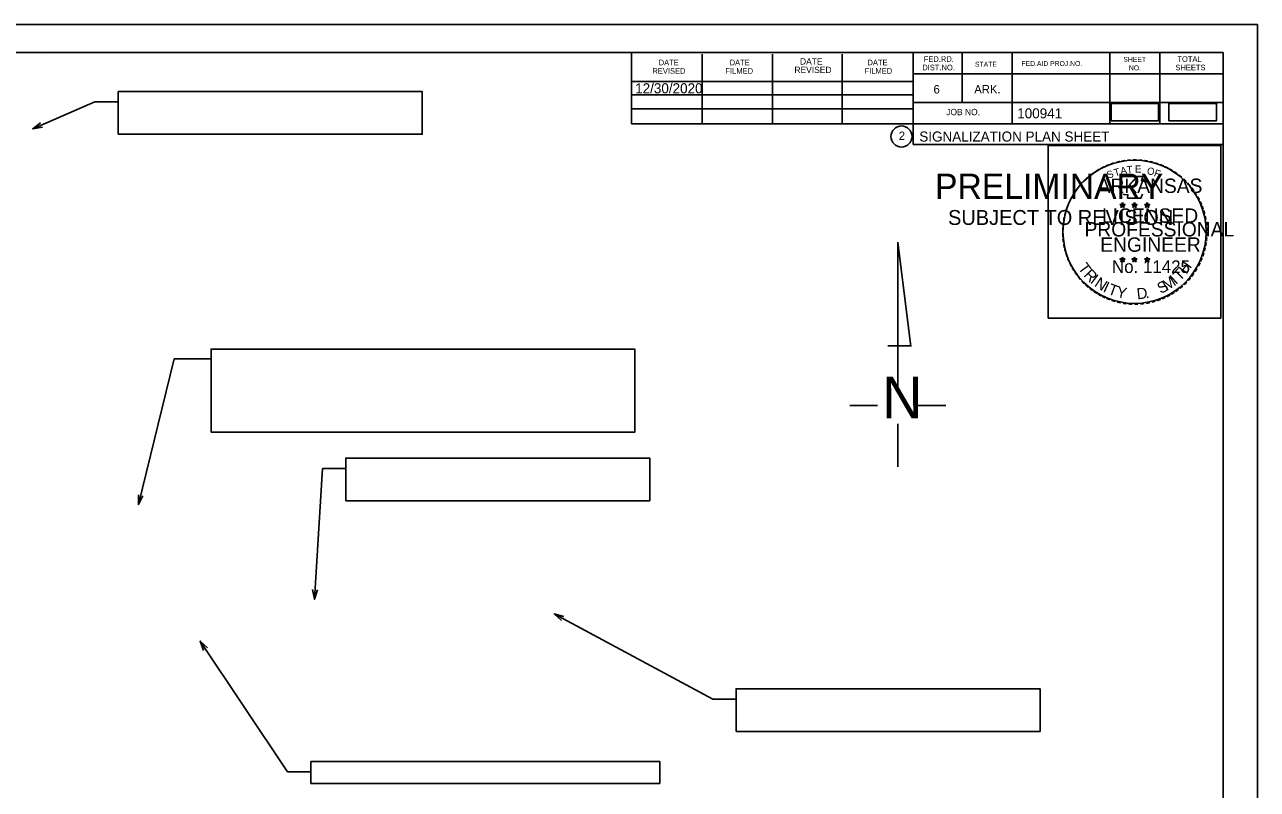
# Model space of a CAD drawing. Extents: x 1845362 to 1846362, y 750211 to 750851.
# Drawn here: x 1845848 to 1846362, y 750532 to 750851 of the extents above; entities that cross this region are included whole.
import ezdxf

# ---------------------------------------------------------------- set-up
doc = ezdxf.new("R2010")
doc.units = 0
for name, color, linetype in [('R_Border', 7, 'Continuous'), ('R_Border PE', 7, 'Continuous'), ('R_Border Prem', 7, 'Continuous'), ('R_Dimension', 7, 'Continuous'), ('R_Draft', 7, 'Continuous'), ('R_No Plot', 7, 'Continuous'), ('T_Drafting', 7, 'Continuous')]:
    doc.layers.add(name, color=color, linetype=linetype)

msp = doc.modelspace()

# ---------------------------------------------------------------- linework, layer by layer
at = {"layer": 'R_Border'}
for p, q in [((1845398.86, 750839.27), (1846347.4, 750839.27)), ((1845856.42, 750838.49), (1845856.42, 750838.49)), ((1845856.42, 750838.49), (1845856.42, 750838.49)), ((1846100.62, 750809.63), (1846100.62, 750839.27)), ((1846130.2, 750809.63), (1846130.2, 750838.67)), ((1846159.48, 750809.63), (1846159.48, 750838.67)), ((1846188.52, 750809.63), (1846188.52, 750838.67)), ((1846218.1, 750839.27), (1846218.1, 750800.87)), ((1846238.62, 750839.27), (1846238.62, 750818.45)), ((1846259.44, 750839.27), (1846259.44, 750809.63)), ((1846300.18, 750839.27), (1846300.18, 750809.63)), ((1846321, 750839.27), (1846321, 750809.63)), ((1846347.4, 750222.89), (1846347.4, 750839.27)), ((1846347.4, 750830.45), (1846218.1, 750830.45)), ((1846347.4, 750830.51), (1846347.4, 750830.51)), ((1846100.62, 750827.21), (1846218.1, 750827.21)), ((1846100.62, 750821.63), (1846218.1, 750821.63)), ((1846347.4, 750818.45), (1846218.1, 750818.45)), ((1846226.98, 750818.45), (1846347.4, 750818.45)), ((1846100.62, 750809.63), (1846100.62, 750815.81)), ((1846100.62, 750815.81), (1846218.1, 750815.81)), ((1846347.4, 750809.63), (1846100.62, 750809.63)), ((1846218.1, 750800.87), (1846347.4, 750800.87))]:
    msp.add_line(p, q, dxfattribs=at)
msp.add_circle((1846213.26, 750804.27), 4.4, dxfattribs=at)
at = {"layer": 'R_Border PE'}
for p, q in [((1846305.43, 750776.71), (1846305.3, 750775.95)), ((1846305.43, 750775.62), (1846305.43, 750776.71)), ((1846305.43, 750776.71), (1846305.57, 750775.96)), ((1846310.44, 750776.71), (1846310.31, 750775.95)), ((1846310.44, 750775.62), (1846310.44, 750776.71)), ((1846310.44, 750776.71), (1846310.58, 750775.96)), ((1846315.73, 750776.67), (1846315.61, 750775.92)), ((1846315.73, 750775.58), (1846315.73, 750776.67)), ((1846315.73, 750776.67), (1846315.88, 750775.92)), ((1846304.38, 750775.95), (1846305.43, 750775.62)), ((1846304.38, 750775.95), (1846305.14, 750775.81)), ((1846304.38, 750775.95), (1846305.09, 750775.58)), ((1846304.78, 750774.72), (1846305.43, 750775.62)), ((1846304.78, 750774.72), (1846305.16, 750775.46)), ((1846304.78, 750774.72), (1846305.42, 750775.38)), ((1846306.07, 750774.72), (1846305.42, 750775.37)), ((1846306.47, 750775.95), (1846305.43, 750775.62)), ((1846306.07, 750774.72), (1846305.43, 750775.62)), ((1846306.47, 750775.95), (1846305.61, 750775.8)), ((1846306.07, 750774.72), (1846305.65, 750775.6)), ((1846306.47, 750775.95), (1846305.86, 750775.64)), ((1846309.39, 750775.95), (1846310.44, 750775.62)), ((1846309.39, 750775.95), (1846310.15, 750775.81)), ((1846309.39, 750775.95), (1846310.1, 750775.58)), ((1846309.79, 750774.72), (1846310.44, 750775.62)), ((1846309.79, 750774.72), (1846310.17, 750775.46)), ((1846309.79, 750774.72), (1846310.43, 750775.38)), ((1846311.08, 750774.72), (1846310.43, 750775.37)), ((1846311.48, 750775.95), (1846310.44, 750775.62)), ((1846311.08, 750774.72), (1846310.44, 750775.62)), ((1846311.48, 750775.95), (1846310.62, 750775.8)), ((1846311.08, 750774.72), (1846310.66, 750775.6)), ((1846311.48, 750775.95), (1846310.87, 750775.64)), ((1846314.68, 750775.91), (1846315.73, 750775.58)), ((1846314.68, 750775.91), (1846315.44, 750775.78)), ((1846314.68, 750775.91), (1846315.39, 750775.55)), ((1846315.08, 750774.69), (1846315.73, 750775.58)), ((1846315.08, 750774.69), (1846315.46, 750775.42)), ((1846315.08, 750774.69), (1846315.72, 750775.34)), ((1846316.37, 750774.69), (1846315.72, 750775.33)), ((1846316.77, 750775.91), (1846315.73, 750775.58)), ((1846316.37, 750774.69), (1846315.73, 750775.58)), ((1846316.77, 750775.91), (1846315.91, 750775.77)), ((1846316.37, 750774.69), (1846315.96, 750775.56)), ((1846316.77, 750775.91), (1846316.16, 750775.61)), ((1846304.37, 750753.23), (1846305.41, 750752.9)), ((1846304.37, 750753.23), (1846305.13, 750753.09)), ((1846304.37, 750753.23), (1846305.08, 750752.86)), ((1846304.77, 750752.01), (1846305.41, 750752.9)), ((1846304.77, 750752.01), (1846305.14, 750752.74)), ((1846304.77, 750752.01), (1846305.41, 750752.66)), ((1846305.41, 750753.99), (1846305.29, 750753.24)), ((1846305.41, 750752.9), (1846305.41, 750753.99)), ((1846305.41, 750753.99), (1846305.56, 750753.24)), ((1846306.46, 750753.23), (1846305.41, 750752.9)), ((1846306.05, 750752.01), (1846305.41, 750752.9)), ((1846306.05, 750752.01), (1846305.41, 750752.65)), ((1846306.46, 750753.23), (1846305.6, 750753.08)), ((1846306.05, 750752.01), (1846305.64, 750752.88)), ((1846306.46, 750753.23), (1846305.84, 750752.92)), ((1846309.37, 750753.23), (1846310.42, 750752.9)), ((1846309.37, 750753.23), (1846310.13, 750753.09)), ((1846309.37, 750753.23), (1846310.09, 750752.86)), ((1846309.77, 750752.01), (1846310.42, 750752.9)), ((1846309.77, 750752.01), (1846310.15, 750752.74)), ((1846309.77, 750752.01), (1846310.42, 750752.66)), ((1846310.42, 750753.99), (1846310.3, 750753.24)), ((1846310.42, 750752.9), (1846310.42, 750753.99)), ((1846310.42, 750753.99), (1846310.57, 750753.24)), ((1846311.46, 750753.23), (1846310.42, 750752.9)), ((1846311.06, 750752.01), (1846310.42, 750752.9)), ((1846311.06, 750752.01), (1846310.42, 750752.65)), ((1846311.46, 750753.23), (1846310.6, 750753.08)), ((1846311.06, 750752.01), (1846310.65, 750752.88)), ((1846311.46, 750753.23), (1846310.85, 750752.92)), ((1846314.68, 750753.2), (1846315.72, 750752.87)), ((1846314.68, 750753.2), (1846315.43, 750753.06)), ((1846314.68, 750753.2), (1846315.39, 750752.83)), ((1846315.07, 750751.98), (1846315.72, 750752.87)), ((1846315.07, 750751.98), (1846315.45, 750752.71)), ((1846315.07, 750751.98), (1846315.72, 750752.63)), ((1846315.72, 750753.96), (1846315.6, 750753.21)), ((1846315.72, 750752.87), (1846315.72, 750753.96)), ((1846315.72, 750753.96), (1846315.87, 750753.21)), ((1846316.76, 750753.2), (1846315.72, 750752.87)), ((1846316.36, 750751.98), (1846315.72, 750752.87)), ((1846316.36, 750751.98), (1846315.72, 750752.62)), ((1846316.76, 750753.2), (1846315.91, 750753.05)), ((1846316.36, 750751.98), (1846315.95, 750752.85)), ((1846316.76, 750753.2), (1846316.15, 750752.89))]:
    msp.add_line(p, q, dxfattribs=at)
for points in [[(1846304.5, 750787.58), (1846305.31, 750785.1)], [(1846315.04, 750784.82), (1846315.46, 750785.67), (1846313.41, 750785.6), (1846313.85, 750787.58), (1846304.5, 750787.58)], [(1846305.43, 750776.71), (1846306.07, 750774.72), (1846304.38, 750775.95), (1846306.47, 750775.95), (1846304.78, 750774.72), (1846305.43, 750776.71)], [(1846305.98, 750780.31), (1846305.98, 750780.05), (1846307.67, 750780), (1846307.51, 750778.58), (1846313.12, 750778.58), (1846313.72, 750780.18)], [(1846310.44, 750776.71), (1846311.08, 750774.72), (1846309.39, 750775.95), (1846311.48, 750775.95), (1846309.79, 750774.72), (1846310.44, 750776.71)], [(1846315.73, 750776.67), (1846316.37, 750774.69), (1846314.68, 750775.91), (1846316.77, 750775.91), (1846315.08, 750774.69), (1846315.73, 750776.67)], [(1846305.41, 750753.99), (1846306.05, 750752.01), (1846304.37, 750753.23), (1846306.46, 750753.23), (1846304.77, 750752.01), (1846305.41, 750753.99)], [(1846310.42, 750753.99), (1846311.06, 750752.01), (1846309.37, 750753.23), (1846311.46, 750753.23), (1846309.77, 750752.01), (1846310.42, 750753.99)], [(1846315.72, 750753.96), (1846316.36, 750751.98), (1846314.68, 750753.2), (1846316.76, 750753.2), (1846315.07, 750751.98), (1846315.72, 750753.96)]]:
    msp.add_lwpolyline(points, dxfattribs=at)
for centre, radius in [((1846305.42, 750775.61), 0.517), ((1846305.42, 750775.61), 0.434), ((1846305.42, 750775.61), 0.347), ((1846305.42, 750775.61), 0.297), ((1846305.42, 750775.61), 0.224), ((1846305.42, 750775.61), 0.149), ((1846305.42, 750775.61), 0.0889), ((1846310.43, 750775.61), 0.517), ((1846310.43, 750775.61), 0.434), ((1846310.43, 750775.61), 0.347), ((1846310.43, 750775.61), 0.297), ((1846310.43, 750775.61), 0.224), ((1846310.43, 750775.61), 0.149), ((1846310.43, 750775.61), 0.0889), ((1846315.73, 750775.58), 0.517), ((1846315.73, 750775.58), 0.434), ((1846315.73, 750775.58), 0.347), ((1846315.73, 750775.58), 0.297), ((1846315.73, 750775.58), 0.224), ((1846315.73, 750775.58), 0.149), ((1846315.73, 750775.58), 0.0889), ((1846305.41, 750752.89), 0.517), ((1846305.41, 750752.89), 0.434), ((1846305.41, 750752.89), 0.347), ((1846305.41, 750752.89), 0.297), ((1846305.41, 750752.89), 0.224), ((1846305.41, 750752.89), 0.149), ((1846305.41, 750752.89), 0.0889), ((1846310.42, 750752.89), 0.517), ((1846310.42, 750752.89), 0.434), ((1846310.42, 750752.89), 0.347), ((1846310.42, 750752.89), 0.297), ((1846310.42, 750752.89), 0.224), ((1846310.42, 750752.89), 0.149), ((1846310.42, 750752.89), 0.0889), ((1846315.72, 750752.86), 0.517), ((1846315.72, 750752.86), 0.434), ((1846315.72, 750752.86), 0.347), ((1846315.72, 750752.86), 0.297), ((1846315.72, 750752.86), 0.224), ((1846315.72, 750752.86), 0.149), ((1846315.72, 750752.86), 0.0889)]:
    msp.add_circle(centre, radius, dxfattribs=at)
at = {"layer": 'R_Dimension'}
for p, q in [((1845876.89, 750818.68), (1845851, 750807.51)), ((1845876.89, 750818.68), (1845886.64, 750818.68)), ((1845895.03, 750650.68), (1845909.94, 750711.48)), ((1845925.17, 750711.48), (1845909.94, 750711.48)), ((1845971.77, 750665.75), (1845968.42, 750611.21)), ((1845971.77, 750665.75), (1845981.52, 750665.75)), ((1846134.54, 750569.52), (1846068.43, 750605.06)), ((1845957.26, 750539.13), (1845920.84, 750593.72)), ((1846134.54, 750569.52), (1846144.29, 750569.52)), ((1845957.26, 750539.13), (1845967.01, 750539.13))]:
    msp.add_line(p, q, dxfattribs=at)
for points in [[(1845855.06, 750808.18), (1845851, 750807.51), (1845854.27, 750810.02)], [(1845895.01, 750654.8), (1845895.03, 750650.68), (1845896.95, 750654.33)], [(1845969.66, 750615.14), (1845968.42, 750611.21), (1845967.67, 750615.26)], [(1846071.48, 750602.29), (1846068.43, 750605.06), (1846072.42, 750604.05)], [(1845922.23, 750589.84), (1845920.84, 750593.72), (1845923.89, 750590.95)]]:
    msp.add_lwpolyline(points, dxfattribs=at)
at = {"layer": 'R_Draft'}
for p, q in [((1846211.74, 750760.24), (1846217.21, 750716.6)), ((1846211.74, 750699.23), (1846211.74, 750760.24)), ((1846207.51, 750716.93), (1846217.21, 750716.93)), ((1846191.68, 750692.04), (1846203.25, 750692.04)), ((1846219.45, 750692.04), (1846231.81, 750692.04)), ((1846211.74, 750666.5), (1846211.74, 750684.44))]:
    msp.add_line(p, q, dxfattribs=at)
at = {"layer": 'R_No Plot'}
for p, q in [((1845361.65, 750850.95), (1846361.65, 750850.95)), ((1846274.23, 750731.82), (1846274.23, 750731.82))]:
    msp.add_line(p, q, dxfattribs=at)
for points in [[(1845361.63, 750850.95), (1846361.65, 750850.95), (1846361.65, 750210.94), (1845361.63, 750210.94)], [(1846274.46, 750800.5), (1846346.46, 750800.5), (1846346.46, 750728.5), (1846274.46, 750728.5)]]:
    msp.add_lwpolyline(points, close=True, dxfattribs=at)
msp.add_circle((1846310.46, 750764.5), 29.86, dxfattribs=at)
at = {"layer": 'T_Drafting'}
for points in [[(1845886.64, 750805.22), (1846013.38, 750805.22), (1846013.38, 750823.02), (1845886.64, 750823.02)], [(1846300.71, 750810.78), (1846320.46, 750810.78), (1846320.46, 750818.07), (1846300.71, 750818.07)], [(1846324.81, 750810.78), (1846344.56, 750810.78), (1846344.56, 750818.07), (1846324.81, 750818.07)], [(1845925.38, 750680.87), (1846102.04, 750680.87), (1846102.04, 750715.6), (1845925.38, 750715.6)], [(1845981.52, 750652.29), (1846108.26, 750652.29), (1846108.26, 750670.09), (1845981.52, 750670.09)], [(1846144.29, 750556.06), (1846271.03, 750556.06), (1846271.03, 750573.86), (1846144.29, 750573.86)], [(1845967.01, 750534.35), (1846112.42, 750534.35), (1846112.42, 750543.47), (1845967.01, 750543.47)]]:
    msp.add_lwpolyline(points, close=True, dxfattribs=at)

# ---------------------------------------------------------------- texts
at = {"layer": 'R_Border'}
for s, height, p in [('DATE', 2.346, (1846112.02, 750833.99)), ('DATE', 2.346, (1846141.6, 750833.99)), ('REVISED', 2.638, (1846168.6, 750830.75)), ('DATE', 2.638, (1846170.94, 750834.29)), ('DATE', 2.346, (1846199.08, 750833.99)), ('DIST.NO.', 2.346, (1846221.94, 750831.89)), ('FED.RD.', 2.346, (1846222.54, 750835.43)), ('STATE', 2.052, (1846243.9, 750833.39)), ('FED.AID PROJ.NO.', 2.052, (1846263.28, 750833.69)), ('SHEET', 2.052, (1846305.76, 750835.43)), ('NO.', 2.052, (1846308.1, 750831.89)), ('SHEETS', 2.346, (1846327.48, 750831.89)), ('TOTAL', 2.346, (1846328.32, 750835.43)), ('REVISED', 2.346, (1846109.38, 750830.45)), ('FILMED', 2.346, (1846139.86, 750830.45)), ('FILMED', 2.346, (1846197.88, 750830.45)), ('12/30/2020', 4.2, (1846102.19, 750822.29)), ('6', 3.52, (1846226.62, 750822.23)), ('ARK.', 3.517, (1846243.6, 750822.23)), ('JOB NO.', 2.638, (1846231.9, 750813.17)), ('100941', 4.2, (1846261.52, 750811.84)), ('2', 3.52, (1846212.11, 750802.81)), ('SIGNALIZATION PLAN SHEET', 4.2, (1846220.69, 750802.16))]:
    msp.add_text(s, height=height, dxfattribs=at).set_placement(p)
at = {"layer": 'R_Border PE'}
for s, height, rotation, p in [('-', 4.8, 28.7918, (1846296.95, 750789.21)), ('-', 4.8, 24.3072, (1846298.84, 750790.16)), ('-', 4.8, 19.1761, (1846300.75, 750790.96)), ('-', 4.8, 13.6302, (1846303, 750791.69)), ('-', 4.8, 10.2193, (1846305.03, 750792.17)), ('T', 3, 6.0228, (1846307.33, 750788.86)), ('-', 4.8, 5.8968, (1846307.22, 750792.5)), ('-', 4.8, 0.1862, (1846309.53, 750792.72)), ('E', 3, 0.8323, (1846310.65, 750789.19)), ('-', 4.8, 357.743, (1846311.7, 750792.68)), ('-', 4.8, 352.1617, (1846313.93, 750792.51)), ('-', 4.8, 347.2049, (1846316.09, 750792.17)), ('-', 4.8, 342.3362, (1846318, 750791.7)), ('-', 4.8, 337.8551, (1846320.2, 750791.04)), ('-', 4.8, 334.1211, (1846322.09, 750790.22)), ('-', 4.8, 42.9622, (1846290.69, 750784.53)), ('-', 4.8, 38.9507, (1846291.99, 750785.78)), ('-', 4.8, 36.2317, (1846293.42, 750786.91)), ('-', 4.8, 34.0636, (1846295.15, 750788.1)), ('S', 3, 21.594, (1846299.57, 750786.62)), ('T', 3, 16.4036, (1846302.31, 750787.61)), ('A', 3, 11.2132, (1846304.79, 750788.36)), ('O', 3, 350.4515, (1846315.46, 750788.56)), ('F', 3, 340.0707, (1846318.32, 750787.88)), ('-', 4.8, 329.6409, (1846323.83, 750789.37)), ('-', 4.8, 325.8627, (1846325.76, 750788.29)), ('-', 4.8, 320.5297, (1846327.59, 750787.01)), ('-', 4.8, 315.5786, (1846329.39, 750785.55)), ('-', 4.8, 54.2325, (1846286.9, 750779.93)), ('-', 4.8, 50.6142, (1846288.14, 750781.63)), ('-', 4.8, 48.4231, (1846289.35, 750783.09)), ('-', 4.8, 309.8797, (1846331.09, 750783.9)), ('-', 4.8, 306.6522, (1846332.67, 750782.09)), ('-', 4.8, 67.7743, (1846284.21, 750774.68)), ('-', 4.8, 62.8713, (1846284.99, 750776.51)), ('-', 4.8, 58.0706, (1846285.93, 750778.35)), ('-', 4.2, 303.6753, (1846334.13, 750780.39)), ('-', 4.8, 299.6684, (1846335.08, 750778.57)), ('-', 4.8, 294.6628, (1846336.06, 750776.73)), ('-', 4.8, 75.461, (1846282.96, 750770.64)), ('-', 4.8, 72.3945, (1846283.55, 750772.79)), ('-', 4.8, 290.5728, (1846336.83, 750775)), ('-', 4.8, 285.1233, (1846337.53, 750773.26)), ('-', 4.8, 89.0622, (1846282.26, 750764.33)), ('-', 4.8, 85.1863, (1846282.34, 750766.43)), ('-', 4.8, 81.2013, (1846282.57, 750768.51)), ('-', 4.8, 280.5493, (1846338.13, 750771.03)), ('-', 4.8, 276.5962, (1846338.62, 750768.73)), ('-', 4.8, 274.3301, (1846338.8, 750766.56)), ('-', 4.8, 94.1959, (1846282.37, 750762.15)), ('-', 4.8, 98.9479, (1846282.58, 750760.15)), ('-', 4.8, 263.5172, (1846338.84, 750762.67)), ('-', 4.8, 269.9407, (1846338.9, 750764.67)), ('-', 4.8, 101.7149, (1846282.99, 750757.95)), ('-', 4.8, 105.4578, (1846283.48, 750756.17)), ('-', 4.8, 255.7626, (1846338.3, 750758.67)), ('-', 4.8, 260.9953, (1846338.63, 750760.71)), ('-', 4.8, 109.0874, (1846284.12, 750754.28)), ('-', 4.8, 114.0643, (1846284.88, 750752.49)), ('-', 4.8, 115.7289, (1846285.8, 750750.63)), ('T', 4.62, 306.0406, (1846286.69, 750749.41)), ('H', 4.62, 54.6088, (1846332.05, 750746.52)), ('-', 4.8, 244.6197, (1846336.3, 750752.61)), ('-', 4.8, 247.8887, (1846337.09, 750754.5)), ('-', 4.8, 252.8681, (1846337.75, 750756.51)), ('-', 4.8, 120.4471, (1846286.87, 750748.88)), ('-', 4.8, 125.8934, (1846288.08, 750747.19)), ('-', 4.8, 130.7181, (1846289.46, 750745.54)), ('R', 4.62, 314.005, (1846288.98, 750746.27)), ('I', 4.62, 321.9694, (1846291.68, 750743.47)), ('N', 4.62, 326.5002, (1846293.38, 750742.06)), ('M', 4.62, 32.6563, (1846323.85, 750739.71)), ('I', 4.62, 42.1136, (1846327.7, 750742.25)), ('T', 4.62, 46.6444, (1846329.39, 750743.69)), ('-', 4.8, 233.8452, (1846333.91, 750748.39)), ('-', 4.8, 239.0712, (1846335.12, 750750.35)), ('-', 4.8, 134.2238, (1846291.01, 750743.9)), ('-', 4.8, 138.9338, (1846292.59, 750742.51)), ('-', 4.8, 144.6463, (1846294.26, 750741.29)), ('I', 4.62, 335.3603, (1846297.01, 750739.7)), ('T', 4.62, 339.8912, (1846298.99, 750738.72)), ('Y', 4.62, 347.8556, (1846302.64, 750737.38)), ('D', 4.62, 6.3969, (1846311.6, 750736.3)), ('S', 4.62, 26.9312, (1846321.33, 750738.5)), ('-', 4.8, 215.7363, (1846327.97, 750742.06)), ('-', 4.8, 221.0851, (1846329.62, 750743.48)), ('-', 4.8, 225.7653, (1846331.18, 750745)), ('-', 4.8, 231.2538, (1846332.62, 750746.7)), ('-', 4.8, 148.0898, (1846295.94, 750740.18)), ('-', 4.8, 151.5704, (1846297.68, 750739.2)), ('-', 4.8, 154.6002, (1846299.24, 750738.46)), ('-', 4.8, 158.5612, (1846301.12, 750737.7)), ('-', 4.8, 162.7983, (1846303.18, 750737.06)), ('-', 4.8, 167.5555, (1846305.32, 750736.57)), ('.', 4.62, 13.7642, (1846315.17, 750736.69)), ('-', 4.8, 195.4743, (1846318.94, 750737.36)), ('-', 4.8, 200.7184, (1846320.97, 750738.09)), ('-', 4.8, 204.2516, (1846322.82, 750738.9)), ('-', 4.8, 207.3568, (1846324.7, 750739.86)), ('-', 4.8, 212.2491, (1846326.37, 750740.9)), ('-', 4.8, 173.1155, (1846307.64, 750736.24)), ('-', 4.8, 176.5183, (1846309.88, 750736.08)), ('-', 4.8, 181.5918, (1846312.11, 750736.14)), ('-', 4.8, 185.8167, (1846314.54, 750736.37)), ('-', 4.8, 191.2858, (1846316.75, 750736.76))]:
    msp.add_text(s, height=height, rotation=rotation, dxfattribs=at).set_placement(p)
for s, height, p in [('ARKANSAS', 6, (1846295.06, 750780.72)), ('LICENSED', 6, (1846296.85, 750768.27)), ('DWB', 0.03, (1846305.39, 750775.6)), ('DWB', 0.03, (1846310.4, 750775.6)), ('DWB', 0.03, (1846315.69, 750775.57)), ('PROFESSIONAL', 6, (1846289.58, 750762.56)), ('ENGINEER', 6, (1846296.14, 750756.18)), ('No. 11425', 5.271, (1846301.03, 750747.33)), ('DWB', 0.03, (1846305.38, 750752.88)), ('DWB', 0.03, (1846310.38, 750752.88)), ('DWB', 0.03, (1846315.68, 750752.85))]:
    msp.add_text(s, height=height, dxfattribs=at).set_placement(p)
at = {"layer": 'R_Border Prem'}
for s, height, p in [('PRELIMINARY', 10.5, (1846227.25, 750778.26)), ('SUBJECT TO REVISION', 6.2253, (1846232.68, 750767.37))]:
    msp.add_text(s, height=height, dxfattribs=at).set_placement(p)
at = {"layer": 'R_Draft'}
msp.add_text('N', height=17.45, dxfattribs=at).set_placement((1846205.13, 750686.66))

doc.saveas('drawing.dxf')
